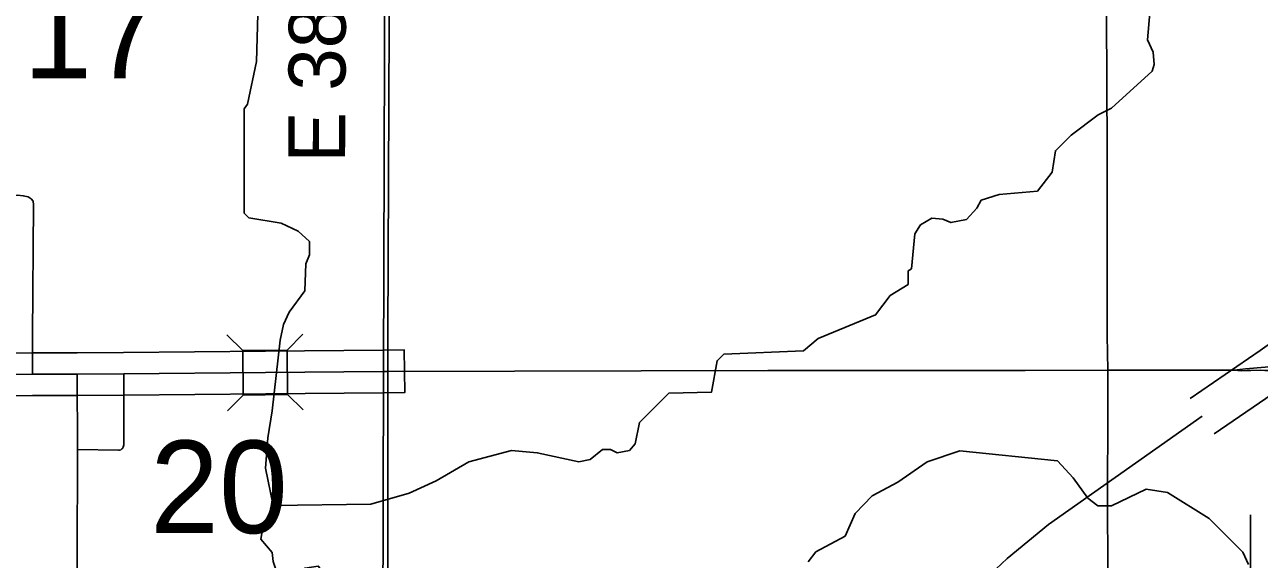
# Model space of a CAD drawing. Extents: x -1403959 to 81668, y -1400582 to 11018.
# Drawn here: x 7531.9 to 7699.7, y 8595.5 to 8668.1 of the extents above; entities that cross this region are included whole.
import ezdxf

# ---------------------------------------------------------------- set-up
doc = ezdxf.new("R2010")
doc.units = 0
for name, color, linetype in [('tdCiCityDivCarto', 7, 'Continuous'), ('tdCiCoBndryTxt', 7, 'Continuous'), ('tdCiRRCL', 7, 'Continuous'), ('tdCiSecText', 7, 'Continuous'), ('tdCiSectLine', 7, 'Continuous'), ('tdCiSectNmbr', 7, 'Continuous'), ('tdCiSectTwpRng', 7, 'Continuous'), ('tdCoDivCarto', 7, 'Continuous'), ('tdCoSecRteCL', 7, 'Continuous'), ('tdCoSectLinePart', 7, 'Continuous'), ('tdCoSectNmbr', 7, 'Continuous'), ('tdCoSurfBitum', 7, 'Continuous')]:
    doc.layers.add(name, color=color, linetype=linetype)

msp = doc.modelspace()

# ---------------------------------------------------------------- linework, layer by layer
at = {"layer": 'tdCiCityDivCarto'}
for points in [[(7521.03, 8644.89), (7523.4, 8644.92), (7530.88, 8644.96), (7531.66, 8644.89), (7532.32, 8644.73), (7532.73, 8644.47)], [(7532.91, 8620.64), (7532.94, 8625.89), (7533.05, 8643.67), (7532.99, 8644.14), (7532.73, 8644.47)], [(7538.89, 8572.53), (7538.89, 8574.39), (7538.98, 8595.45), (7539.04, 8610.4), (7539, 8620.66)], [(7545.19, 8610.63), (7545.25, 8610.74), (7545.34, 8611.06), (7545.33, 8620.7)], [(7539.04, 8610.4), (7544.59, 8610.32), (7544.76, 8610.34), (7544.92, 8610.39), (7545.06, 8610.5)], [(7545.06, 8610.5), (7545.18, 8610.61), (7545.19, 8610.63)]]:
    msp.add_lwpolyline(points, dxfattribs=at)
at = {"layer": 'tdCiCoBndryTxt'}
for points in [[(7545.33, 8620.7), (7564.6, 8620.87), (7580.58, 8621.02)], [(7496.76, 8620.51), (7508.81, 8620.55), (7520.84, 8620.61), (7532.91, 8620.64), (7539, 8620.66), (7545.33, 8620.7)]]:
    msp.add_lwpolyline(points, dxfattribs=at)
at = {"layer": 'tdCiRRCL'}
msp.add_lwpolyline([(7580.82, 8678.75), (7580.61, 8621.02), (7580.52, 8585.97)], dxfattribs=at)
at = {"layer": 'tdCiSecText'}
for points in [[(7559.33, 8625.99), (7561.49, 8623.87), (7567.54, 8623.92)], [(7569.66, 8626.08), (7567.54, 8623.92), (7567.59, 8617.87)], [(7559.42, 8615.66), (7561.54, 8617.82), (7561.49, 8623.87)], [(7569.7, 8615.8), (7567.59, 8617.87), (7561.54, 8617.82)]]:
    msp.add_lwpolyline(points, dxfattribs=at)
at = {"layer": 'tdCiSectLine'}
msp.add_lwpolyline([(7520.83, 8623.51), (7532.9, 8623.54), (7538.99, 8623.56), (7545.3, 8623.6), (7564.57, 8623.77), (7580.55, 8623.92), (7583.46, 8623.95), (7583.51, 8618.14), (7580.61, 8618.11), (7564.62, 8617.97), (7564.62, 8617.97), (7545.35, 8617.8), (7545.34, 8617.8), (7539.02, 8617.76), (7539.01, 8617.76), (7532.92, 8617.74), (7532.92, 8617.74), (7520.85, 8617.71)], dxfattribs=at)
at = {"layer": 'tdCiSectNmbr'}
for points in [[(7579, 8697.01), (7580.41, 8693.99), (7580.77, 8693.15), (7581.09, 8692.25), (7581.27, 8691.47), (7581.43, 8690.44), (7581.53, 8689.49), (7581.53, 8688.16), (7581.47, 8683.34), (7581.43, 8678.75), (7581.21, 8625.93), (7581.21, 8621.02)], [(7580.61, 8621.02), (7581.21, 8621.02)], [(7581.09, 8572.9), (7581.19, 8578.95), (7581.21, 8586.02), (7581.23, 8607.14), (7581.21, 8621.02)], [(7581.21, 8621.02), (7632.88, 8621.14), (7643.08, 8621.16), (7644.19, 8621.16), (7666.68, 8621.17), (7667.83, 8621.17), (7679.07, 8621.18)], [(7679.07, 8621.18), (7689.98, 8621.18)], [(7689.98, 8621.18), (7691.32, 8621.18), (7695.79, 8621.18), (7696.27, 8621.21)], [(7696.27, 8621.21), (7697.26, 8621.12), (7697.99, 8621.14), (7698.53, 8621.15)]]:
    msp.add_lwpolyline(points, dxfattribs=at)
at = {"layer": 'tdCiSectTwpRng'}
for points in [[(7679.07, 8621.18), (7679.02, 8625.91), (7679.02, 8651.13), (7678.84, 8678.56)], [(7679.05, 8605.97), (7679.05, 8606.5), (7679.11, 8612.87), (7679.07, 8621.18)], [(7701.48, 8621.74), (7701.21, 8621.7), (7700.48, 8621.62), (7697.79, 8621.37), (7696.27, 8621.21)], [(7698.53, 8621.15), (7699.87, 8621.18), (7700.45, 8621.17), (7701.48, 8621.17)], [(7679.04, 8572.62), (7679.05, 8573.75), (7679.06, 8576.06), (7679.08, 8582.65), (7679.09, 8586.3), (7679.09, 8593.71), (7679.08, 8596.97), (7679.06, 8600.76), (7679.05, 8605.36), (7679.05, 8605.97)], [(7698.5, 8576.47), (7698.92, 8576.87), (7699.21, 8577.3), (7699.37, 8577.79), (7699.44, 8578.26), (7699.44, 8579.78), (7699.41, 8582.52), (7699.45, 8584.65), (7699.44, 8587), (7699.39, 8587.81), (7699.23, 8588.55), (7698.56, 8591.16), (7698.48, 8591.54), (7698.46, 8592.08), (7698.46, 8601.55)]]:
    msp.add_lwpolyline(points, dxfattribs=at)
at = {"layer": 'tdCoDivCarto'}
for points in [[(7690.28, 8617.36), (7699.81, 8623.85), (7707.75, 8629.55), (7712.38, 8633.2), (7716.28, 8636.54), (7722.53, 8642.6)], [(7693.53, 8612.55), (7703.15, 8619.1), (7711.22, 8624.9), (7716.11, 8628.76), (7720.15, 8632.21), (7725.36, 8637.25)]]:
    msp.add_lwpolyline(points, dxfattribs=at)
at = {"layer": 'tdCoSecRteCL'}
msp.add_lwpolyline([(7577.43, 8528.2), (7621.81, 8559.41), (7629.43, 8564.82), (7644.8, 8575.63), (7649.57, 8580.05), (7660.78, 8591.25), (7665.41, 8595.62), (7671.02, 8600.22), (7691.91, 8614.96)], dxfattribs=at)
at = {"layer": 'tdCoSurfBitum'}
for points in [[(7684.8, 8669.77), (7684.49, 8666.1), (7685.25, 8664.42), (7685.4, 8662.74), (7685.1, 8661.83), (7679.6, 8656.79), (7677.77, 8655.88), (7674.1, 8653.13), (7671.96, 8651), (7671.5, 8648.1), (7669.51, 8645.5), (7664.32, 8645.05), (7661.88, 8644.29), (7661.27, 8643.22), (7659.89, 8641.69), (7657.75, 8641.24), (7656.68, 8641.7), (7655.16, 8641.85), (7653.63, 8640.93), (7652.87, 8639.71), (7652.41, 8634.98), (7651.95, 8634.68), (7651.95, 8632.84), (7649.5, 8631.32), (7647.52, 8628.72), (7639.73, 8625.52), (7637.74, 8623.84), (7626.9, 8623.39), (7625.98, 8622.48), (7625.21, 8618.2), (7619.41, 8618.06), (7615.44, 8614.09), (7614.83, 8611.19), (7614.06, 8610.27), (7612.38, 8609.97), (7611.47, 8610.43), (7610.4, 8610.43), (7608.72, 8609.06), (7607.19, 8608.75), (7601.54, 8609.98), (7598.03, 8610.28), (7592.22, 8608.76), (7587.79, 8606.17), (7584.13, 8604.49), (7578.93, 8602.97), (7565.65, 8602.82), (7564.58, 8607.86), (7564.89, 8611.99), (7565.5, 8615.65), (7566.58, 8625.27), (7567.03, 8627.4), (7567.8, 8629.08), (7569.94, 8631.98), (7570.09, 8635.65), (7570.55, 8636.87), (7570.55, 8638.7), (7569.03, 8640.08), (7566.74, 8641.15), (7562.31, 8641.91), (7561.7, 8642.52), (7561.7, 8656.72), (7562.16, 8657.33), (7563.39, 8663.13), (7563.54, 8669.55)], [(7638.34, 8595.14), (7639.41, 8596.51), (7643.38, 8598.65), (7644.75, 8601.7), (7647.05, 8604.14), (7650.56, 8605.97), (7654.53, 8608.72), (7658.96, 8610.24), (7672.25, 8608.86), (7674.38, 8606.57), (7676.37, 8603.82), (7677.74, 8602.75), (7679.57, 8602.75), (7684.31, 8605.03), (7687.21, 8604.57), (7692.86, 8601.06), (7697.44, 8596.48), (7698.2, 8594.8)], [(7575.41, 8579.15), (7574.5, 8583.58), (7573.73, 8585.26), (7573.58, 8592.44), (7571.75, 8594.58), (7569.92, 8594.27), (7568.24, 8593.05), (7566.87, 8593.21), (7566.1, 8593.82), (7565.64, 8595.19), (7565.49, 8596.41), (7563.97, 8598.25), (7564.27, 8600.08), (7565.65, 8602.82)]]:
    msp.add_lwpolyline(points, dxfattribs=at)

# ---------------------------------------------------------------- texts
at = {"layer": 'tdCoSectLinePart'}
for s, rotation, p in [('17', 359.998, (7531.67, 8660.86)), ('20', 359.9982, (7548.92, 8599.05))]:
    msp.add_text(s, height=12.575, rotation=rotation, dxfattribs=at).set_placement(p)
at = {"layer": 'tdCoSectNmbr'}
msp.add_text('E 38 ST', height=7.738, rotation=89.7248, dxfattribs=at).set_placement((7575.41, 8649.38))

doc.saveas('drawing.dxf')
